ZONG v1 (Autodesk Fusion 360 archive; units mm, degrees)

design "ZONG" references "main 2", "arm cover", "arm main v1", "arm2 v1"
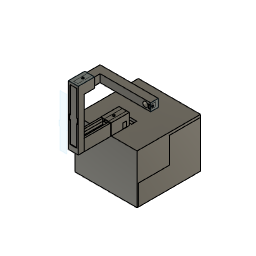
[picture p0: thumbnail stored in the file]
sketch "草图1" plane through (0, 0, 0) normal (0, 0, 1) x axis (1, 0, 0)
  line L1 (60, 60) -> (-60, 60)
  line L2 (60, -60) -> (60, 60)
  line L3 (-60, -60) -> (60, -60)
  line L4 (-60, 60) -> (-60, -60)
  line L5 (60, -60) -> (-60, 60)
  line L6 (-60, -60) -> (60, 60)
  point P6 (0, 0)
  point P1 (0, 0)
  point P4 (60, -60)
  point P5 (-60, -60)
  horizontal L1
  perpendicular L1 L2
  parallel L1 L3
  parallel L2 L4
  coincident L5 P6
  coincident L6 P6
  coincident P1 P6
  dimension "d1" distance P4 P5 = 120
  dimension "d2" distance L1 L3 = 120
sketch "草图2" plane through (0, -60, 0) normal (0, -1, 0) x axis (1, 0, 0)
  line L1 (60, 0) -> (-60, 0)
  line L2 (60, 90) -> (60, 0)
  line L3 (-60, 90) -> (60, 90)
  line L4 (-60, 0) -> (-60, 90)
  line L5 (55, 90) -> (-55, 90)
  line L6 (55, 5) -> (55, 90)
  line L7 (-55, 5) -> (55, 5)
  line L8 (-55, 90) -> (-55, 5)
  point P6 (-55, 90)
  horizontal L5
  vertical L6
  horizontal L7
  vertical L8
  coincident L3 P6
  dimension "d5" distance L4 L8 = 5
  dimension "d19" distance L1 L7 = 5
sketch "草图11" plane through (0, -60, 0) normal (0, -1, 0) x axis (1, 0, 0)
  line L1 (-55, 90) -> (-55, 5)
  line L2 (-60, 90) -> (-55, 90)
  line L3 (-60, 0) -> (-60, 90)
  line L4 (60, 0) -> (-60, 0)
  line L5 (60, 90) -> (60, 0)
  line L6 (55, 90) -> (60, 90)
  line L7 (55, 5) -> (55, 90)
  line L8 (-55, 5) -> (55, 5)
  line L9 (-58, 85) -> (-55, 85)
  line L10 (-58, 75) -> (-58, 85)
  line L11 (-55, 75) -> (-58, 75)
  line L12 (-55, 85) -> (-55, 75)
  point P10 (-55, 85)
  horizontal L9
  vertical L10
  horizontal L11
  vertical L12
  coincident L1 P10
  dimension "d45" distance L10 L12 = 3
  dimension "d46" distance L9 L11 = 10
  dimension "d47" distance L2 L9 = 5
sketch "草图12" plane through (-60, 0, 0) normal (-1, 0, 0) x axis (0, -1, 0)
  line L1 (60, 0) -> (-60, 0)
  line L2 (60, 90) -> (60, 0)
  line L3 (-60, 90) -> (60, 90)
  line L4 (-60, 0) -> (-60, 90)
  line L5 (60, 90) -> (0, 90)
  line L6 (60, 40) -> (60, 90)
  line L7 (0, 40) -> (60, 40)
  line L8 (0, 90) -> (0, 40)
  point P8 (60, 40)
  point P6 (0, 90)
  horizontal L5
  vertical L6
  horizontal L7
  vertical L8
  coincident L2 P8
  midpoint L3 P6
  dimension "d50" distance L5 L7 = 50
sketch "草图13" plane through (0, 0, 0) normal (0, -1, 0) x axis (1, 0, 0)
  line L1 (-55, 90) -> (-55, 40)
  line L2 (-60, 90) -> (-55, 90)
  line L3 (-60, 40) -> (-60, 90)
  line L4 (-55, 40) -> (-60, 40)
  line L5 (-58, 85) -> (-55, 85)
  line L6 (-58, 65) -> (-58, 85)
  line L7 (-55, 65) -> (-58, 65)
  line L8 (-55, 85) -> (-55, 65)
  point P6 (-55, 85)
  horizontal L5
  vertical L6
  horizontal L7
  vertical L8
  coincident L1 P6
  dimension "d53" distance L5 L7 = 20
  dimension "d54" distance L2 L5 = 5
  dimension "d55" distance L6 L8 = 3
mirror "镜像1" mirrorStitchTolerance 0.1
sketch "草图14" plane through (0, -60, 0) normal (0, -1, 0) x axis (1, 0, 0)
  line L1 (-60, 40) -> (-55, 40)
  line L2 (-60, 0) -> (-60, 40)
  line L3 (60, 0) -> (-60, 0)
  line L4 (60, 40) -> (60, 0)
  line L5 (55, 40) -> (60, 40)
  line L6 (55, 5) -> (55, 40)
  line L7 (-55, 5) -> (55, 5)
  line L8 (-55, 40) -> (-55, 5)
  line L9 (-58, 40) -> (-56, 40)
  line L10 (-58, 35) -> (-58, 40)
  line L11 (-56, 35) -> (-58, 35)
  line L12 (-56, 40) -> (-56, 35)
  point P10 (-56, 40)
  horizontal L9
  vertical L10
  horizontal L11
  vertical L12
  coincident L1 P10
  dimension "d60" distance L9 L11 = 5
  dimension "d61" distance L10 L12 = 2
  dimension "d62" distance L2 L10 = 2
mirror "镜像2" mirrorStitchTolerance 0.1
sketch "草图1" plane through (0, -60, 0) normal (0, -1, 0) x axis (1, 0, 0)
  line L1 (58, 35) -> (58, 40)
  line L2 (56, 35) -> (58, 35)
  line L3 (56, 40) -> (56, 35)
  line L4 (55, 40) -> (56, 40)
  line L5 (55, 5) -> (55, 40)
  line L6 (-55, 5) -> (55, 5)
  line L7 (-55, 40) -> (-55, 5)
  line L8 (-56, 40) -> (-55, 40)
  line L9 (-56, 35) -> (-56, 40)
  line L10 (-58, 35) -> (-56, 35)
  line L11 (-58, 40) -> (-58, 35)
  line L12 (-60, 40) -> (-58, 40)
  line L13 (-60, 0) -> (-60, 40)
  line L14 (60, 0) -> (-60, 0)
  line L15 (60, 40) -> (60, 0)
  line L16 (58, 40) -> (60, 40)
  line L17 (-57.9, 35) -> (-56.1, 35)
  line L18 (-57.9, 39.9) -> (-57.9, 35)
  line L19 (-56.1, 39.9) -> (-57.9, 39.9)
  line L20 (-56.1, 35) -> (-56.1, 39.9)
  line L21 (57.9, 40) -> (56.1, 40)
  line L22 (57.9, 35.1) -> (57.9, 40)
  line L23 (56.1, 35.1) -> (57.9, 35.1)
  line L24 (56.1, 40) -> (56.1, 35.1)
  point P18 (-56.1, 35)
  horizontal L17
  vertical L18
  horizontal L19
  vertical L20
  coincident L10 P18
  horizontal L21
  vertical L22
  horizontal L23
  vertical L24
  dimension "d82" distance L17 L19 = 4.9
  dimension "d83" distance L18 L20 = 1.8
  dimension "d84" distance L9 L20 = 0.1
  dimension "d85" distance L22 L24 = 1.8
  dimension "d86" distance L21 L23 = 4.9
  dimension "d87" distance L1 L22 = 0.1
mirror_component "镜像零部件"
derived_instance "DerivedInstance1"
remove_instance "移除实例"
extrude "拉伸6" new body of existing geometry blind 50
sketch "草图2" plane through (0, -60, 0) normal (0, -1, 0) x axis (1, 0, 0)
  line L1 (58, 35) -> (58, 40)
  line L2 (56, 35) -> (58, 35)
  line L3 (56, 40) -> (56, 35)
  line L4 (55, 40) -> (56, 40)
  line L5 (55, 5) -> (55, 40)
  line L6 (-55, 5) -> (55, 5)
  line L7 (-55, 40) -> (-55, 5)
  line L8 (-56, 40) -> (-55, 40)
  line L9 (-56, 35) -> (-56, 40)
  line L10 (-58, 35) -> (-56, 35)
  line L11 (-58, 40) -> (-58, 35)
  line L12 (-60, 40) -> (-58, 40)
  line L13 (-60, 0) -> (-60, 40)
  line L14 (60, 0) -> (-60, 0)
  line L15 (60, 40) -> (60, 0)
  line L16 (58, 40) -> (60, 40)
  line L17 (-60, 95) -> (60, 95)
  line L18 (-60, 0) -> (-60, 95)
  line L19 (60, 0) -> (-60, 0)
  line L20 (60, 95) -> (60, 0)
  point P15 (-60, 0)
  point P20 (-60, 0)
  horizontal L17
  vertical L18
  horizontal L19
  vertical L20
  coincident P15 P20
  dimension "d73" distance L17 L19 = 95
extrude "拉伸2" add sketch "草图2" along normal blind 2.5
sketch "草图3" plane through (0, -60, 0) normal (0, 1, 0) x axis (-1, 0, 0)
  line L1 (-60, 0) -> (-60, 95)
  line L2 (60, 95) -> (60, 0)
  line L3 (-60, 95) -> (60, 95)
  line L4 (60, 95) -> (-60, 95)
  line L5 (60, 90) -> (60, 95)
  line L6 (-60, 90) -> (60, 90)
  line L7 (-60, 95) -> (-60, 90)
  line L8 (60, 0) -> (-60, 0)
  line L9 (-56, 40) -> (-58, 40)
  line L10 (-56, 35) -> (-56, 40)
  line L11 (-58, 35) -> (-56, 35)
  line L12 (-58, 40) -> (-58, 35)
  point P8 (60, 90)
  point P2 (-60, 95)
  point P6 (-60, 95)
  horizontal L4
  vertical L5
  horizontal L6
  vertical L7
  coincident L2 P8
  coincident P2 P6
extrude "拉伸3" add sketch "草图3" profile of L1 L2 L3 L4 L5 L6 L7 along normal blind 120
sketch "草图4" plane through (60, 0, 0) normal (1, 0, 0) x axis (0, 1, 0)
  line L1 (-60, 90) -> (-60, 0)
  line L2 (60, 90) -> (-60, 90)
  line L3 (60, 95) -> (60, 90)
  line L4 (-62.5, 95) -> (60, 95)
  line L5 (-62.5, 0) -> (-62.5, 95)
  line L6 (-60, 0) -> (-62.5, 0)
  line L7 (-60, 90) -> (0, 90)
  line L8 (-60, 40) -> (-60, 90)
  line L9 (0, 40) -> (-60, 40)
  line L10 (0, 90) -> (0, 40)
  point P10 (-60, 40)
  point P8 (0, 90)
  horizontal L7
  vertical L8
  horizontal L9
  vertical L10
  coincident L1 P10
  midpoint L2 P8
extrude "拉伸4" add sketch "草图4" profile of L1 L2 L7 L8 L9 L10 against normal blind 5
sketch "草图5" plane through (0, 0, 0) normal (0, 1, 0) x axis (-1, 0, 0)
  line L1 (-60, 40) -> (-60, 90)
  line L2 (-55, 40) -> (-60, 40)
  line L3 (-55, 90) -> (-55, 40)
  line L4 (-60, 90) -> (-55, 90)
  line L5 (-55, 65.1) -> (-58, 65.1)
  line L6 (-55, 84.9) -> (-55, 65.1)
  line L7 (-58, 84.9) -> (-55, 84.9)
  line L8 (-58, 65.1) -> (-58, 84.9)
  point P8 (-55, 84.9)
  horizontal L5
  vertical L6
  horizontal L7
  vertical L8
  coincident L3 P8
  dimension "d80" distance L4 L7 = 5.1
  dimension "d81" distance L5 L7 = 19.8
extrude "拉伸5" add sketch "草图5" profile of L3 L5 L6 L7 L8 along normal blind 9.8
mirror "镜像2" mirrorStitchTolerance 0.1
mirror "镜像3" mirrorStitchTolerance 0.1
mirror "镜像4" mirrorStitchTolerance 0.1
sketch "草图2" plane through (0, 0, 95) normal (0, 0, 1) x axis (-1, 0, 0)
  line L1 (60, 62.5) -> (60, -60)
  line L2 (-60, 62.5) -> (60, 62.5)
  line L3 (-60, -60) -> (-60, 62.5)
  line L4 (60, -60) -> (-60, -60)
  line L5 (-10, 50) -> (10, 50)
  line L6 (-10, 15) -> (-10, 50)
  line L7 (10, 15) -> (-10, 15)
  line L8 (10, 50) -> (10, 15)
  horizontal L5
  vertical L6
  horizontal L7
  vertical L8
  dimension "d96" distance L6 L8 = 20
  dimension "d97" distance L5 L7 = 35
extrude "拉伸1" new body sketch "草图2" profile of L5 L6 L7 L8 along normal blind 20
sketch "草图3" plane through (0, -15, 0) normal (0, 1, 0) x axis (-1, 0, 0)
  line L1 (10, 95) -> (-10, 95)
  line L2 (10, 115) -> (10, 95)
  line L3 (-10, 115) -> (10, 115)
  line L4 (-10, 95) -> (-10, 115)
  line L5 (-6.2, 111.8736) -> (-6.2, 112)
  line L6 (-6, 101.3) -> (-6.2, 101.3)
  line L7 (6.5, 101.3) -> (6.35, 101.3)
  line L8 (6.35, 112) -> (-6.35, 112)
  line L9 (6.35, 101.3) -> (6.35, 112)
  line L10 (-6.35, 112) -> (-6.35, 101.3)
  line L11 (5.4209, 102.0827) -> (-6.35, 112)
  line L12 (-6.35, 101.3) -> (6.35, 112)
  line L13 (3.9991, 99.3) -> (3.9991, 101.3)
  line L14 (-4.0009, 99.3) -> (3.9991, 99.3)
  line L15 (-4.0009, 101.3) -> (-4.0009, 99.3)
  line L16 (3.9991, 99.3) -> (-4.0009, 101.3)
  line L17 (-4.0009, 99.3) -> (3.9991, 101.3)
  line L18 (3.9991, 101.3) -> (6.35, 101.3)
  line L19 (-6.35, 101.3) -> (-4.0009, 101.3)
  line L20 (3.9991, 99.3) -> (3.9991, 101.3)
  line L21 (-4.0009, 101.3) -> (-4.0009, 99.3)
  line L22 (3.9991, 99.3) -> (3.9991, 101.3)
  point P13 (0, 106.65)
  point P14 (-6.2, 112)
  point P15 (-6.2, 111.8736)
  point P17 (6.35, 101.3)
  point P22 (-0.0009, 100.3)
  point P18 (-4.0009, 101.3)
  point P21 (-4.0009, 99.3)
  vertical L5
  horizontal L6
  collinear L6 L7
  horizontal L8
  perpendicular L8 L9
  parallel L8 L18
  parallel L9 L10
  coincident L11 P13
  coincident L12 P13
  coincident L8 P14
  coincident L11 P15
  coincident L9 P17
  parallel L13 L15
  coincident L16 P22
  coincident L17 P22
  coincident P18 L18
  collinear L18 L19
  perpendicular L14 L20
  perpendicular L19 L21
  dimension "d176" distance L8 L18 = 10.7
  dimension "d177" distance L9 L10 = 12.7
  dimension "d178" distance L3 L8 = 3
  dimension "d179" distance L2 L9 = 3.65
  dimension "d180" distance P18 P21 = 2
  dimension "d181" distance L13 L15 = 8
sketch "草图4" plane through (0, 0, 95) normal (0, 0, -1) x axis (1, 0, 0)
  line L1 (-10, 15) -> (-10, 50)
  line L2 (10, 15) -> (-10, 15)
  line L3 (10, 50) -> (10, 15)
  line L4 (-10, 50) -> (10, 50)
  line L5 (-7.391, 41) -> (7.609, 41)
  line L6 (-7.391, 36) -> (-7.391, 41)
  line L7 (7.609, 36) -> (-7.391, 36)
  line L8 (7.609, 41) -> (7.609, 36)
  horizontal L5
  vertical L6
  horizontal L7
  vertical L8
  dimension "d107" distance L5 L7 = 5
  dimension "d108" distance L6 L8 = 15
sketch "草图5" plane through (0, 0, 0) normal (0, 0, -1) x axis (1, 0, 0)
  line L1 (-60, 60) -> (60, 60)
  line L2 (-60, -60) -> (-60, 60)
  line L3 (60, -60) -> (-60, -60)
  line L4 (60, 60) -> (60, -60)
  line L5 (-32, -40) -> (-45, -40)
  line L6 (-32, -52) -> (-32, -40)
  line L7 (-45, -52) -> (-32, -52)
  line L8 (-45, -40) -> (-45, -52)
  horizontal L5
  vertical L6
  horizontal L7
  vertical L8
  dimension "d113" distance L5 L7 = 12
  dimension "d114" distance L6 L8 = 13
  dimension "d115" distance L2 L8 = 15
sketch "草图6" plane through (0, 0, 90) normal (0, 0, -1) x axis (1, 0, 0)
  line L1 (-60, 0) -> (-55, 0)
  line L2 (-60, -60) -> (-60, 0)
  line L3 (60, -60) -> (-60, -60)
  line L4 (60, 0) -> (60, -60)
  line L5 (55, 0) -> (60, 0)
  line L6 (55, 60) -> (55, 0)
  line L7 (-55, 60) -> (55, 60)
  line L8 (-55, 0) -> (-55, 60)
  line L9 (-7.4, 36) -> (7.6, 36)
  line L10 (-7.4, 46) -> (-7.4, 36)
  line L11 (7.6, 46) -> (-7.4, 46)
  line L12 (7.6, 36) -> (7.6, 46)
  horizontal L9
  vertical L10
  horizontal L11
  vertical L12
  dimension "d161" distance L9 L11 = 10
position "位置"
extrude "拉伸9" cut of existing geometry blind -1
extrude "拉伸10" cut of existing geometry blind -1
extrude "拉伸11" cut of existing geometry blind -1
extrude "拉伸12" cut of existing geometry blind -1
extrude "拉伸13" cut of existing geometry blind -1
extrude "拉伸14" cut of existing geometry blind -1
extrude "拉伸15" cut of existing geometry blind -0.5
extrude "拉伸16" cut of existing geometry blind -0.5
extrude "拉伸17" cut of existing geometry blind -0.5
extrude "拉伸18" cut of existing geometry blind -0.5
extrude "拉伸15" add of existing geometry blind 2
sketch "草图15" plane through (0, -62.5, 0) normal (0, -1, 0) x axis (1, 0, 0)
  line L1 (10, 95) -> (-10, 95)
  line L2 (10, 117) -> (10, 95)
  line L3 (-10, 117) -> (10, 117)
  line L4 (-10, 95) -> (-10, 117)
  line L5 (-4, 113) -> (4, 113)
  line L6 (-4, 116) -> (-4, 113)
  line L7 (4, 116) -> (-4, 116)
  line L8 (4, 113) -> (4, 116)
  line L9 (-4, 116) -> (4, 113)
  line L10 (4, 116) -> (-4, 113)
  point P10 (0, 114.5)
  point P8 (-4, 116)
  point P9 (4, 116)
  horizontal L5
  perpendicular L5 L6
  parallel L5 L7
  parallel L6 L8
  coincident L9 P10
  coincident L10 P10
  dimension "d151" distance P8 P9 = 8
  dimension "d152" distance L5 L7 = 3
extrude "拉伸7" cut sketch "草图15" profile of L5 L6 L7 L8 against normal blind 50
sketch "草图16" plane through (0, 0, 117) normal (0, 0, 1) x axis (-1, 0, 0)
  line L1 (10, 62.5) -> (10, 27.5)
  line L2 (-10, 62.5) -> (10, 62.5)
  line L3 (-10, 27.5) -> (-10, 62.5)
  line L4 (10, 27.5) -> (-10, 27.5)
  circle C1 centre (0, 47.5) radius 2
  point P6 (0, 47.5)
  dimension "d155" diameter C1 = 4
  dimension "d156" distance L2 P6 = 15
extrude "拉伸8" cut sketch "草图16" profile of C1 against normal blind 7
extrude "拉伸9" add of existing geometry blind 1
extrude "拉伸10" add of existing geometry blind 1
sketch "草图18" plane through (0, 0, 90) normal (0, 0, -1) x axis (1, 0, 0)
  line L1 (-60, 0) -> (-55, 0)
  line L2 (-60, -60) -> (-60, 0)
  line L3 (60, -60) -> (-60, -60)
  line L4 (60, 0) -> (60, -60)
  line L5 (55, 0) -> (60, 0)
  line L6 (55, 60) -> (55, 0)
  line L7 (-55, 60) -> (55, 60)
  line L8 (-55, 0) -> (-55, 60)
  line L9 (7.6149, 46) -> (-7.4, 46)
  line L10 (7.6149, 39) -> (7.6149, 46)
  line L11 (-7.4, 39) -> (7.6149, 39)
  line L12 (-7.4, 46) -> (-7.4, 39)
  horizontal L9
  vertical L10
  horizontal L11
  vertical L12
  dimension "d184" distance L9 L11 = 7
sketch "草图19" plane through (0, 0, 95) normal (0, 0, 1) x axis (-1, 0, 0)
  line L1 (60, 62.5) -> (60, -60)
  line L2 (-60, 62.5) -> (60, 62.5)
  line L3 (-60, -60) -> (-60, 62.5)
  line L4 (60, -60) -> (-60, -60)
  line L5 (-10, 13) -> (10, 13)
  line L6 (-10, 23) -> (-10, 13)
  line L7 (10, 23) -> (-10, 23)
  line L8 (10, 13) -> (10, 23)
  line L9 (-10, 23) -> (10, 13)
  line L10 (10, 23) -> (-10, 13)
  point P10 (0, 18)
  horizontal L5
  perpendicular L5 L6
  parallel L5 L7
  parallel L6 L8
  coincident L9 P10
  coincident L10 P10
extrude "拉伸21" cut sketch "草图19" profile of L5 L6 L7 L8 against normal blind 30
extrude "拉伸12" cut sketch "草图3" profile of L7 L8 L9 L19 L10 L13 L14 L15 L20 L21 L22 against normal blind 55
sketch "草图20" plane through (0, 0, 90) normal (0, 0, -1) x axis (1, 0, 0)
  line L1 (10, 13) -> (10, 23)
  line L2 (-10, 13) -> (10, 13)
  line L3 (-10, 23) -> (-10, 13)
  line L4 (10, 23) -> (-10, 23)
  line L5 (-60, 0) -> (-55, 0)
  line L6 (-60, -60) -> (-60, 0)
  line L7 (60, -60) -> (-60, -60)
  line L8 (60, 0) -> (60, -60)
  line L9 (55, 0) -> (60, 0)
  line L10 (55, 60) -> (55, 0)
  line L11 (-55, 60) -> (55, 60)
  line L12 (-55, 0) -> (-55, 60)
  line L13 (9.625, 39.5) -> (-9.625, 39.5)
  line L14 (9.625, 32.5) -> (9.625, 39.5)
  line L15 (-9.625, 32.5) -> (9.625, 32.5)
  line L16 (-9.625, 39.5) -> (-9.625, 32.5)
  line L17 (9.625, 32.5) -> (-9.625, 39.5)
  line L18 (-9.625, 32.5) -> (9.625, 39.5)
  line L19 (60, 62.5) -> (-60, 62.5)
  point P18 (0, 36)
  horizontal L13
  perpendicular L13 L14
  parallel L13 L15
  parallel L14 L16
  coincident L17 P18
  coincident L18 P18
  dimension "d185" distance L13 L15 = 7
  dimension "d186" distance L13 L19 = 23
extrude "拉伸22" cut sketch "草图20" profile of L13 L14 L15 L16 against normal blind 15
component_insert "插入零部件1"
component_insert "插入零部件2"
component_insert "插入零部件3"
component_insert "插入零部件6"
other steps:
extrude "拉伸5" add of existing geometry blind 2
extrude "拉伸13" cut sketch "草图20" profile of L13 L14 L15 L16 against normal blind 15
derived_base_feature "Derived Base Feature"
create_component "创建零部件1"
create_component "创建零部件2"
create_component "创建零部件3"

design "arm main v1"
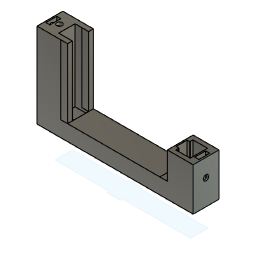
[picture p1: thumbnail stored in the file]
sketch "草图1" plane through (0, 0, 0) normal (0, 0, 1) x axis (1, 0, 0)
  line L1 (57.5, 9.5) -> (-57.5, 9.5)
  line L2 (57.5, -9.5) -> (57.5, 9.5)
  line L3 (-57.5, -9.5) -> (57.5, -9.5)
  line L4 (-57.5, 9.5) -> (-57.5, -9.5)
  line L5 (57.5, -9.5) -> (-57.5, 9.5)
  line L6 (-57.5, -9.5) -> (57.5, 9.5)
  point P6 (0, 0)
  point P1 (0, 0)
  point P4 (57.5, -9.5)
  point P5 (-57.5, -9.5)
  horizontal L1
  perpendicular L1 L2
  parallel L1 L3
  parallel L2 L4
  coincident L5 P6
  coincident L6 P6
  coincident P1 P6
  dimension "d1" distance P4 P5 = 115
  dimension "d2" distance L1 L3 = 19
extrude "拉伸1" new body sketch "草图1" profile of L1 L2 L3 L4 along normal blind 10
sketch "草图2" plane through (0, 0, 10) normal (0, 0, 1) x axis (-1, 0, 0)
  line L1 (-57.5, 9.5) -> (57.5, 9.5)
  line L2 (-57.5, -9.5) -> (-57.5, 9.5)
  line L3 (57.5, -9.5) -> (-57.5, -9.5)
  line L4 (57.5, 9.5) -> (57.5, -9.5)
  line L5 (-38.5, 9.5) -> (-57.5, 9.5)
  line L6 (-38.5, -9.5) -> (-38.5, 9.5)
  line L7 (-57.5, -9.5) -> (-38.5, -9.5)
  line L8 (-57.5, 9.5) -> (-57.5, -9.5)
  point P3 (-57.5, 9.5)
  point P6 (-57.5, 9.5)
  point P7 (-38.5, 9.5)
  horizontal L5
  vertical L6
  horizontal L7
  vertical L8
  coincident P3 P6
  dimension "d5" distance P6 P7 = 19
extrude "拉伸2" add sketch "草图2" profile of L1 L2 L3 L5 L6 L7 L8 along normal blind 20
sketch "草图3" plane through (0, 0, 30) normal (0, 0, 1) x axis (-1, 0, 0)
  line L1 (-38.5, -9.5) -> (-57.5, -9.5)
  line L2 (-38.5, 9.5) -> (-38.5, -9.5)
  line L3 (-57.5, 9.5) -> (-38.5, 9.5)
  line L4 (-57.5, -9.5) -> (-57.5, 9.5)
  line L5 (-41.5, 6.353) -> (-52.2, 6.353)
  line L6 (-52.2, -6.347) -> (-41.5, -6.347)
  line L7 (-41.5, -6.347) -> (-52.2, 6.353)
  line L8 (-52.2, -6.347) -> (-41.5, 6.353)
  line L9 (-52.2, -5.5) -> (-52.2, -6.347)
  line L10 (-52.2, 6.353) -> (-52.2, 5.5)
  line L11 (-52.2, -5.5) -> (-52.2, 5.5)
  line L12 (-41.5, 4.5005) -> (-41.5, 6.353)
  line L13 (-41.5, -6.347) -> (-41.5, -4.4995)
  line L14 (-39.5, 3.9901) -> (-41.5, 3.9901)
  line L15 (-39.5, -4.0099) -> (-39.5, 3.9901)
  line L16 (-41.5, -4.0099) -> (-39.5, -4.0099)
  line L17 (-39.5, -4.0099) -> (-41.5, 3.9901)
  line L18 (-41.5, -4.0099) -> (-39.5, 3.9901)
  line L19 (-56.2, 4) -> (-53.2, 4)
  line L20 (-56.2, -4) -> (-56.2, 4)
  line L21 (-53.2, -4) -> (-56.2, -4)
  line L22 (-53.2, 4) -> (-53.2, -4)
  line L23 (-56.2, -4) -> (-53.2, 4)
  line L24 (-53.2, -4) -> (-56.2, 4)
  line L25 (-41.5, 3.9901) -> (-41.5, 4.5005)
  line L26 (-41.5, -4.4995) -> (-41.5, -4.0099)
  point P10 (-46.85, 0.003)
  point P11 (-52.2, 5.5)
  point P20 (-40.5, -0.0099)
  point P15 (-40.5, -0.0099)
  point P25 (-54.7, 0)
  point P26 (-41.5, 3.9901)
  point P18 (-39.5, -4.0099)
  point P19 (-41.5, -4.0099)
  horizontal L5
  perpendicular L5 L12
  parallel L5 L6
  parallel L9 L12
  coincident L7 P10
  coincident L8 P10
  coincident P11 L9
  collinear L9 L10
  collinear L12 L13
  parallel L13 L25
  horizontal L14
  perpendicular L14 L15
  parallel L14 L16
  coincident L17 P20
  coincident L18 P20
  coincident P15 P20
  horizontal L19
  perpendicular L19 L20
  parallel L19 L21
  parallel L20 L22
  coincident L23 P25
  coincident L24 P25
  collinear L25 L26
  coincident L17 P26
  dimension "d24" distance L9 L12 = 10.7
  dimension "d25" distance L5 L6 = 12.7
  dimension "d26" distance L2 L12 = 3
  dimension "d32" distance P18 P19 = 2
  dimension "d33" distance L14 L16 = 8
  dimension "d34" distance P15 L25 = 1
  dimension "d35" distance L19 L21 = 8
  dimension "d36" distance L20 L22 = 3
  dimension "d37" distance L11 L22 = 1
sketch "草图4" plane through (38.5, 0, 0) normal (-1, 0, 0) x axis (0, -1, 0)
  line L1 (9.5, 10) -> (-9.5, 10)
  line L2 (9.5, 30) -> (9.5, 10)
  line L3 (-9.5, 30) -> (9.5, 30)
  line L4 (-9.5, 10) -> (-9.5, 30)
  circle C1 centre (0, 17) radius 2
  point P6 (0, 17)
  dimension "d20" diameter C1 = 4
  dimension "d21" distance L3 P6 = 13
extrude "拉伸6" cut sketch "草图3" profile of L5 L13 L6 L10 L11 L26 L14 L15 L16 against normal blind 47
extrude "拉伸7" cut sketch "草图3" profile of L19 L20 L21 L22 against normal blind 17
sketch "草图5" plane through (57.5, 0, 0) normal (1, 0, 0) x axis (0, 1, 0)
  line L1 (9.5, 0) -> (-9.5, 0)
  line L2 (9.5, 30) -> (9.5, 0)
  line L3 (-9.5, 30) -> (9.5, 30)
  line L4 (-9.5, 0) -> (-9.5, 30)
  circle C1 centre (0, 22) radius 2
  point P6 (0, 22)
  dimension "d42" diameter C1 = 4
  dimension "d43" distance L3 P6 = 8
extrude "拉伸8" cut sketch "草图5" profile of C1 against normal blind 13
sketch "草图6" plane through (0, 0, 10) normal (0, 0, 1) x axis (-1, 0, 0)
  line L1 (-38.5, -9.5) -> (-38.5, 9.5)
  line L2 (57.5, -9.5) -> (-38.5, -9.5)
  line L3 (57.5, 9.5) -> (57.5, -9.5)
  line L4 (-38.5, 9.5) -> (57.5, 9.5)
  line L5 (56.5, -4) -> (53.5, -4)
  line L6 (56.5, 4) -> (56.5, -4)
  line L7 (53.5, 4) -> (56.5, 4)
  line L8 (53.5, -4) -> (53.5, 4)
  line L9 (56.5, 4) -> (53.5, -4)
  line L10 (53.5, 4) -> (56.5, -4)
  circle C1 centre (50.5, 0) radius 2
  point P10 (55, 0)
  point P8 (56.5, 4)
  point P9 (53.5, 4)
  point P11 (50.5, 0)
  horizontal L5
  perpendicular L5 L6
  parallel L5 L7
  parallel L6 L8
  coincident L9 P10
  coincident L10 P10
  dimension "d48" distance P8 P9 = 3
  dimension "d49" distance L5 L7 = 8
  dimension "d131" diameter C1 = 4
  dimension "d132" distance L8 P11 = 3
extrude "拉伸10" cut sketch "草图6" profile of L5 L6 L7 L8 against normal blind 8
sketch "草图7" plane through (-57.5, 0, 0) normal (-1, 0, 0) x axis (0, -1, 0)
  line L1 (9.5, 0) -> (-9.5, 0)
  line L2 (9.5, 10) -> (9.5, 0)
  line L3 (-9.5, 10) -> (9.5, 10)
  line L4 (-9.5, 0) -> (-9.5, 10)
  circle C1 centre (0, 6) radius 2
  point P6 (0, 6)
  dimension "d56" diameter C1 = 4
  dimension "d57" distance L3 P6 = 4
sketch "草图9" plane through (0, 0, 0) normal (0, 0, -1) x axis (1, 0, 0)
  line L1 (-57.5, 9.5) -> (57.5, 9.5)
  line L2 (-57.5, -9.5) -> (-57.5, 9.5)
  line L3 (57.5, -9.5) -> (-57.5, -9.5)
  line L4 (57.5, 9.5) -> (57.5, -9.5)
  line L5 (-47.5, 6.3532) -> (52.5, 6.3532)
  line L6 (-47.5, -6.6468) -> (-47.5, 6.3532)
  line L7 (52.5, -6.6468) -> (-47.5, -6.6468)
  line L8 (52.5, 6.3532) -> (52.5, -6.6468)
  line L9 (41.5, -6.347) -> (52.2, -6.347)
  line L10 (41.5, -4.4995) -> (41.5, -6.347)
  line L11 (41.5, -4.0099) -> (41.5, -4.4995)
  line L12 (39.5, -4.0099) -> (41.5, -4.0099)
  line L13 (39.5, 3.9901) -> (39.5, -4.0099)
  line L14 (41.5, 3.9901) -> (39.5, 3.9901)
  line L15 (41.5, 4.5005) -> (41.5, 3.9901)
  line L16 (41.5, 6.353) -> (41.5, 4.5005)
  line L17 (52.2, 6.353) -> (41.5, 6.353)
  line L18 (52.2, -6.347) -> (52.2, 6.353)
  horizontal L5
  vertical L6
  horizontal L7
  vertical L8
  dimension "d70" distance L6 L8 = 100
  dimension "d71" distance L5 L7 = 13
extrude "拉伸12" cut sketch "草图9" profile of L5 L6 L7 against normal blind 3
sketch "草图10" plane through (0, 0, 3) normal (0, 0, -1) x axis (1, 0, 0)
  line L1 (41.5, -6.347) -> (52.2, -6.347)
  line L2 (52.2, 6.353) -> (41.5, 6.353)
  line L3 (-47.5, -6.6468) -> (-47.5, 6.3532)
  line L4 (56.2, -6.347) -> (52.2, -6.347)
  line L5 (56.2, 6.353) -> (56.2, -6.347)
  line L6 (52.2, 6.353) -> (56.2, 6.353)
  line L7 (52.2, -6.347) -> (52.2, 6.353)
  line L8 (52.5, 6.3532) -> (52.5, -6.6468)
  line L9 (41.5, 3.9901) -> (39.5, 3.9901)
  line L10 (41.5, 4.5005) -> (41.5, 3.9901)
  line L11 (41.5, 6.353) -> (41.5, 4.5005)
  line L12 (52.2, -6.347) -> (52.2, 6.353)
  line L13 (41.5, -4.4995) -> (41.5, -6.347)
  line L14 (41.5, -4.0099) -> (41.5, -4.4995)
  line L15 (39.5, -4.0099) -> (41.5, -4.0099)
  line L16 (39.5, 3.9901) -> (39.5, -4.0099)
  line L17 (-47.5, 6.3532) -> (52.5, 6.3532)
  line L18 (52.5, -6.6468) -> (-47.5, -6.6468)
  point P8 (56.2, 6.353)
  point P2 (52.2, -6.347)
  point P6 (52.2, -6.347)
  horizontal L4
  vertical L5
  horizontal L6
  vertical L7
  coincident L2 P8
  coincident P2 P6
  dimension "d65" distance L5 L7 = 4
extrude "拉伸14" cut sketch "草图10" profile of L1 L2 L3 L4 L5 L6 L7 against normal blind 19
sketch "草图12" plane through (0, 0, 0) normal (0, 0, -1) x axis (1, 0, 0)
  line L1 (-57.5, 9.5) -> (57.5, 9.5)
  line L2 (-57.5, -9.5) -> (-57.5, 9.5)
  line L3 (57.5, -9.5) -> (-57.5, -9.5)
  line L4 (57.5, 9.5) -> (57.5, -9.5)
  line L5 (-47.5, -6.6468) -> (52.5, -6.6468)
  line L6 (-47.5, 6.3532) -> (-47.5, -6.6468)
  line L7 (52.5, 6.3532) -> (-47.5, 6.3532)
  line L8 (2.5, -8) -> (-7.5, -8)
  line L9 (2.5, 8) -> (2.5, -8)
  line L10 (-7.5, 8) -> (2.5, 8)
  line L11 (-7.5, -8) -> (-7.5, 8)
  line L12 (52.5, -6.6468) -> (52.5, 6.3532)
  horizontal L8
  vertical L9
  horizontal L10
  vertical L11
  dimension "d68" distance L9 L11 = 10
  dimension "d69" distance L8 L10 = 16
  dimension "d72" distance L6 L11 = 40
extrude "拉伸17" add of existing geometry blind 1.5
sketch "草图14" plane through (0, 0, -1.5) normal (0, 0, -1) x axis (1, 0, 0)
  line L1 (-57.5, 9.5) -> (57.5, 9.5)
  line L2 (-57.5, -9.5) -> (-57.5, 9.5)
  line L3 (57.5, -9.5) -> (-57.5, -9.5)
  line L4 (57.5, 9.5) -> (57.5, -9.5)
  line L5 (-47.5, -6.6468) -> (52.5, -6.6468)
  line L6 (-47.5, 6.3532) -> (-47.5, -6.6468)
  line L7 (52.5, 6.3532) -> (-47.5, 6.3532)
  line L8 (52.5, -6.6468) -> (52.5, 6.3532)
  circle C1 centre (-51.5, 0) radius 1.5
extrude "拉伸18" add sketch "草图14" profile of C1 against normal blind 1
sketch "草图15" plane through (0, 0, -1.5) normal (0, 0, -1) x axis (1, 0, 0)
  line L1 (-57.5, 9.5) -> (57.5, 9.5)
  line L2 (-57.5, -9.5) -> (-57.5, 9.5)
  line L3 (57.5, -9.5) -> (-57.5, -9.5)
  line L4 (57.5, 9.5) -> (57.5, -9.5)
  line L5 (-47.5, -6.6468) -> (52.5, -6.6468)
  line L6 (-47.5, 6.3532) -> (-47.5, -6.6468)
  line L7 (52.5, 6.3532) -> (-47.5, 6.3532)
  line L8 (2.5, -8) -> (-7.5, -8)
  line L9 (2.5, -6.6468) -> (2.5, -8)
  line L10 (-7.5, -6.6468) -> (2.5, -6.6468)
  line L11 (-7.5, -8) -> (-7.5, -6.6468)
  line L12 (-7.5, 6.3532) -> (2.5, 6.3532)
  line L13 (-7.5, 8) -> (-7.5, 6.3532)
  line L14 (2.5, 8) -> (-7.5, 8)
  line L15 (2.5, 6.3532) -> (2.5, 8)
  line L16 (52.5, -6.6468) -> (52.5, 6.3532)
  point P12 (2.5, -6.6468)
  point P14 (2.5, 6.3532)
  horizontal L8
  vertical L9
  horizontal L10
  vertical L11
  midpoint L5 P12
  horizontal L12
  vertical L13
  horizontal L14
  vertical L15
  midpoint L7 P14
extrude "拉伸19" cut sketch "草图15" profile of L5 L7 L8 L9 L10 L11 L12 L13 L14 L15 against normal blind 1
sketch "草图16" plane through (0, 0, -21) normal (0, 0, -1) x axis (1, 0, 0)
  line L1 (-7.5, 8) -> (2.5, 8)
  line L2 (-7.5, 6.3532) -> (-7.5, 8)
  line L3 (-47.5, 6.3532) -> (-7.5, 6.3532)
  line L4 (-47.5, -6.6468) -> (-47.5, 6.3532)
  line L5 (-7.5, -6.6468) -> (-47.5, -6.6468)
  line L6 (-7.5, -8) -> (-7.5, -6.6468)
  line L7 (2.5, -8) -> (-7.5, -8)
  line L8 (2.5, -6.6468) -> (2.5, -8)
  line L9 (52.5, -6.6468) -> (2.5, -6.6468)
  line L10 (52.5, 6.3532) -> (52.5, -6.6468)
  line L11 (2.5, 6.3532) -> (52.5, 6.3532)
  line L12 (2.5, 8) -> (2.5, 6.3532)
sketch "草图17" plane through (0, 0, 10) normal (0, 0, 1) x axis (-1, 0, 0)
  line L1 (53.5, -4) -> (56.5, -4)
  line L2 (53.5, 4) -> (53.5, -4)
  line L3 (56.5, 4) -> (53.5, 4)
  line L4 (56.5, -4) -> (56.5, 4)
  line L5 (-38.5, -9.5) -> (-38.5, 9.5)
  line L6 (57.5, -9.5) -> (-38.5, -9.5)
  line L7 (57.5, 9.5) -> (57.5, -9.5)
  line L8 (-38.5, 9.5) -> (57.5, 9.5)
extrude "拉伸20" add sketch "草图17" along normal blind 11
sketch "草图19" plane through (0, 9.5, 0) normal (0, 1, 0) x axis (-1, 0, 0)
  line L1 (57.5, 10) -> (-38.5, 10)
  line L2 (57.5, 21) -> (57.5, 10)
  line L3 (-38.5, 21) -> (57.5, 21)
  line L4 (-33, 21) -> (40, 21)
  line L5 (40, 10) -> (-33, 10)
  line L6 (40, 21) -> (40, 10)
  line L7 (-33, 21) -> (-33, 10)
  line L8 (-38.5, 10) -> (-38.5, 21)
  point P6 (40, 21)
  horizontal L4
  horizontal L5
  vertical L6
  coincident L3 P6
extrude "拉伸22" cut sketch "草图19" profile of L1 L3 L4 L5 L6 L7 against normal blind 30
extrude "拉伸25" cut sketch "草图6" profile of C1 along normal blind 16
sketch "草图22" plane through (0, -9.5, 0) normal (0, -1, 0) x axis (1, 0, 0)
  line L1 (33, 10) -> (33, 21)
  line L2 (-40, 10) -> (33, 10)
  line L3 (-40, 21) -> (-40, 10)
  line L4 (-57.5, 21) -> (-40, 21)
  line L5 (-57.5, -1.5) -> (-57.5, 21)
  line L6 (57.5, -1.5) -> (-57.5, -1.5)
  line L7 (57.5, 30) -> (57.5, -1.5)
  line L8 (38.5, 30) -> (57.5, 30)
  line L9 (38.5, 21) -> (38.5, 30)
  line L10 (33, 21) -> (38.5, 21)
  line L11 (38.5, 10) -> (33, 10)
  line L12 (38.5, 21) -> (38.5, 10)
  line L13 (33, 21) -> (38.5, 21)
  line L14 (33, 10) -> (33, 21)
  point P11 (38.5, 21)
  point P14 (38.5, 21)
  point P3 (33, 10)
  point P12 (33, 10)
  horizontal L11
  vertical L12
  horizontal L13
  vertical L14
  coincident P11 P14
  coincident P3 P12
extrude "拉伸26" cut sketch "草图22" profile of L1 L10 L11 L12 L13 L14 against normal blind 70
sketch "草图23" plane through (0, 0, 30) normal (0, 0, 1) x axis (-1, 0, 0)
  line L1 (-53.2, 4) -> (-56.2, 4)
  line L2 (-53.2, -4) -> (-53.2, 4)
  line L3 (-56.2, -4) -> (-53.2, -4)
  line L4 (-56.2, 4) -> (-56.2, -4)
  line L5 (-52.2, -6.347) -> (-41.5, -6.347)
  line L6 (-52.2, 6.353) -> (-52.2, -6.347)
  line L7 (-41.5, 6.353) -> (-52.2, 6.353)
  line L8 (-41.5, 4.5005) -> (-41.5, 6.353)
  line L9 (-41.5, 3.9901) -> (-41.5, 4.5005)
  line L10 (-39.5, 3.9901) -> (-41.5, 3.9901)
  line L11 (-39.5, -4.0099) -> (-39.5, 3.9901)
  line L12 (-41.5, -4.0099) -> (-39.5, -4.0099)
  line L13 (-41.5, -4.4995) -> (-41.5, -4.0099)
  line L14 (-41.5, -6.347) -> (-41.5, -4.4995)
  line L15 (-38.5, -9.5) -> (-57.5, -9.5)
  line L16 (-38.5, 9.5) -> (-38.5, -9.5)
  line L17 (-57.5, 9.5) -> (-38.5, 9.5)
  line L18 (-57.5, -9.5) -> (-57.5, 9.5)
extrude "拉伸27" add sketch "草图23" against normal blind 27
sketch "草图24" plane through (57.5, 0, 0) normal (1, 0, 0) x axis (0, 1, 0)
  line L1 (-9.5, -1.5) -> (-9.5, 30)
  line L2 (9.5, -1.5) -> (-9.5, -1.5)
  line L3 (9.5, 30) -> (9.5, -1.5)
  line L4 (-9.5, 30) -> (9.5, 30)
sketch "草图25" plane through (57.5, 0, 0) normal (1, 0, 0) x axis (0, 1, 0)
  line L1 (-9.5, 30) -> (9.5, 30)
  circle C1 centre (0, 17) radius 2
  point P2 (0, 17)
  dimension "d139" diameter C1 = 4
  dimension "d140" distance P2 L1 = 13
extrude "拉伸28" cut sketch "草图25" profile of C1 against normal blind 11
extrude "拉伸29" cut of existing geometry blind -5
sketch "草图26" plane through (0, 0, 10) normal (0, 0, 1) x axis (-1, 0, 0)
  line L1 (-33, 9.5) -> (40, 9.5)
  line L2 (-33, -9.5) -> (-33, 9.5)
  line L3 (40, -9.5) -> (-33, -9.5)
  line L4 (40, 9.5) -> (40, -9.5)
  line L5 (45, -6) -> (35, -6)
  line L6 (45, 6) -> (45, -6)
  line L7 (35, 6) -> (45, 6)
  line L8 (35, -6) -> (35, 6)
  line L9 (45, 6) -> (35, -6)
  line L10 (35, 6) -> (45, -6)
  point P10 (40, 0)
  horizontal L5
  perpendicular L5 L6
  parallel L5 L7
  parallel L6 L8
  coincident L9 P10
  coincident L10 P10
  midpoint L4 P10
extrude "拉伸30" cut sketch "草图26" profile of L4 L5 L7 L8 against normal blind 27
sketch "草图27" plane through (0, 0, 8) normal (0, 0, -1) x axis (1, 0, 0)
  line L1 (-40, -6) -> (-35, -6)
  line L2 (-40, 6) -> (-40, -6)
  line L3 (-35, 6) -> (-40, 6)
  line L4 (-35, -6) -> (-35, 6)
  line L5 (52.5, 6.3532) -> (52.5, -6.6468)
  line L6 (-47.5, 6.3532) -> (52.5, 6.3532)
  line L7 (-47.5, -6.6468) -> (-47.5, 6.3532)
  line L8 (52.5, -6.6468) -> (-47.5, -6.6468)
  line L9 (52.2, -6.347) -> (52.2, 6.353)
  line L10 (41.5, -6.347) -> (52.2, -6.347)
  line L11 (41.5, -4.4995) -> (41.5, -6.347)
  line L12 (41.5, -4.0099) -> (41.5, -4.4995)
  line L13 (39.5, -4.0099) -> (41.5, -4.0099)
  line L14 (39.5, 3.9901) -> (39.5, -4.0099)
  line L15 (41.5, 3.9901) -> (39.5, 3.9901)
  line L16 (41.5, 4.5005) -> (41.5, 3.9901)
  line L17 (41.5, 6.353) -> (41.5, 4.5005)
  line L18 (52.2, 6.353) -> (41.5, 6.353)
  line L19 (-45, 6) -> (-40, 6)
  line L20 (-45, -6) -> (-45, 6)
  line L21 (-40, -6) -> (-45, -6)
  line L22 (-40, -6) -> (-40, 6)
  point P4 (-40, 6)
  point P22 (-40, 6)
  point P3 (-40, -6)
  point P23 (-40, -6)
  horizontal L19
  vertical L20
  horizontal L21
  coincident P4 P22
  coincident P3 P23
extrude "拉伸31" cut sketch "草图27" profile of L2 L19 L20 L21 L22 against normal blind 34
extrude "拉伸32" cut of existing geometry blind -1
extrude "拉伸33" cut of existing geometry blind -1
extrude "拉伸34" add of existing geometry blind 40
extrude "拉伸35" add of existing geometry blind 5
sketch "草图28" plane through (-57.5, 0, 0) normal (-1, 0, 0) x axis (0, -1, 0)
  line L1 (9.5, 61) -> (9.5, -1.5)
  line L2 (-9.5, 61) -> (9.5, 61)
  line L3 (-9.5, 10) -> (-9.5, 61)
  line L4 (-9.5, -1.5) -> (-9.5, 10)
  line L5 (9.5, -1.5) -> (-9.5, -1.5)
  circle C1 centre (0, 57) radius 2
  point P7 (0, 57)
  dimension "d158" diameter C1 = 4
  dimension "d159" distance L2 P7 = 4
extrude "拉伸36" cut sketch "草图28" profile of C1 against normal blind 7

design "arm cover"
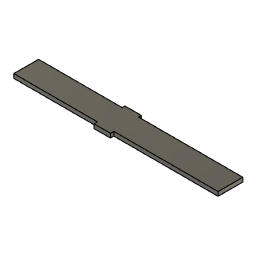
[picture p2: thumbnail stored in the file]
sketch "草图" plane through (0, 0, -20) normal (0, 0, -1) x axis (1, 0, 0)
  line L1 (-57.5, 9.5) -> (57.5, 9.5)
  line L2 (-57.5, -9.5) -> (-57.5, 9.5)
  line L3 (57.5, -9.5) -> (-57.5, -9.5)
  line L4 (57.5, 9.5) -> (57.5, -9.5)
  line L5 (-7.5, 8) -> (-7.5, 6.3532)
  line L6 (2.5, 8) -> (-7.5, 8)
  line L7 (2.5, 6.3532) -> (2.5, 8)
  line L8 (52.5, 6.3532) -> (2.5, 6.3532)
  line L9 (52.5, 5.5) -> (52.5, 6.3532)
  line L10 (52.5, -6.6468) -> (52.5, 5.5)
  line L11 (2.5, -6.6468) -> (52.5, -6.6468)
  line L12 (2.5, -8) -> (2.5, -6.6468)
  line L13 (-7.5, -8) -> (2.5, -8)
  line L14 (-7.5, -6.6468) -> (-7.5, -8)
  line L15 (-47.5, -6.6468) -> (-7.5, -6.6468)
  line L16 (-47.5, 6.3532) -> (-47.5, -6.6468)
  line L17 (-7.5, 6.3532) -> (-47.5, 6.3532)
  line L18 (-47.5, 6.3532) -> (-47.5, -6.6468)
  line L19 (52.5, -6.6468) -> (52.5, 6.3532)
  line L20 (-7.5, -8) -> (-7.5, -6.6468)
  line L21 (2.5, -8) -> (-7.5, -8)
  line L22 (2.5, -6.6468) -> (2.5, -8)
  line L23 (2.5, 8) -> (2.5, 6.3532)
  line L24 (-7.5, 8) -> (2.5, 8)
  line L25 (-7.5, 6.3532) -> (-7.5, 8)
  line L26 (2.5, -6.6468) -> (52.5, -6.6468)
  line L27 (-47.5, -6.6468) -> (-7.5, -6.6468)
  line L28 (-7.5, 6.3532) -> (-47.5, 6.3532)
  line L29 (52.5, 6.3532) -> (2.5, 6.3532)
  circle C1 centre (-51.5, 0) radius 1.5
  point P18 (-47.5, 6.3532)
  point P22 (-47.5, 6.3532)
  point P12 (52.5, -6.6468)
  point P20 (52.5, -6.6468)
  point P15 (-7.5, -8)
  point P26 (-7.5, -8)
  point P13 (2.5, -6.6468)
  point P24 (2.5, -6.6468)
  point P8 (2.5, 8)
  point P30 (2.5, 8)
  point P6 (-7.5, 6.3532)
  point P28 (-7.5, 6.3532)
  horizontal L26
  vertical L18
  horizontal L28
  vertical L19
  coincident P18 P22
  coincident P12 P20
  vertical L20
  horizontal L21
  vertical L22
  coincident P15 P26
  coincident P13 P24
  vertical L23
  horizontal L24
  vertical L25
  coincident P8 P30
  coincident P6 P28
  collinear L26 L27
  collinear L28 L29
extrude "拉伸2" new body sketch "草图" profile of L5 L6 L7 L8 L9 L10 L11 L12 L13 L14 L15 L16 L17 L27 L18 L29 L19 L20 L21 L22 L23 L24 L25 along normal blind 1
extrude "拉伸3" cut of existing geometry blind -1
extrude "拉伸4" cut of existing geometry blind -1
extrude "拉伸5" cut of existing geometry blind -1
extrude "拉伸6" cut of existing geometry blind -1
extrude "拉伸7" cut of existing geometry blind -0.5
extrude "拉伸8" cut of existing geometry blind -0.5
extrude "拉伸9" cut of existing geometry blind -0.5
extrude "拉伸10" cut of existing geometry blind -0.5
extrude "拉伸11" cut of existing geometry blind -0.5
extrude "拉伸12" cut of existing geometry blind -0.5
extrude "拉伸13" cut of existing geometry blind -0.5
extrude "拉伸14" cut of existing geometry blind -0.5
move "移动" TranslateX 0 TranslateY 0 TranslateZ 19.5
extrude "拉伸15" add of existing geometry blind 1

design "main 2"
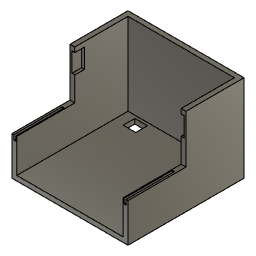
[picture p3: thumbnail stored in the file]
base_feature "基础特征"
sketch "草图" plane through (0, 0, 0) normal (0, 0, -1) x axis (1, 0, 0)
  line L1 (-32, -52) -> (-32, -40)
  line L2 (-45, -52) -> (-32, -52)
  line L3 (-45, -40) -> (-45, -52)
  line L4 (-32, -40) -> (-45, -40)
  line L5 (-60, 60) -> (60, 60)
  line L6 (-60, -60) -> (-60, 60)
  line L7 (60, -60) -> (-60, -60)
  line L8 (60, 60) -> (60, -60)
  line L9 (48, -50) -> (35, -50)
  line L10 (48, -37) -> (48, -50)
  line L11 (35, -37) -> (48, -37)
  line L12 (35, -50) -> (35, -37)
  point P10 (35, -50)
  point P11 (48, -50)
  horizontal L9
  vertical L10
  horizontal L11
  vertical L12
  dimension "d1" distance P10 P11 = 13
  dimension "d2" distance L9 L11 = 13
  dimension "d3" distance L7 L9 = 10
extrude "拉伸" cut sketch "草图" profile of L9 L10 L11 L12 against normal blind 30

design "arm2 v1"
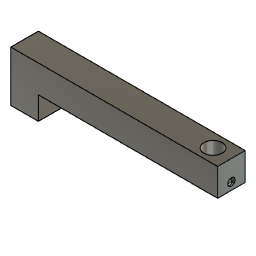
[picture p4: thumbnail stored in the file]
sketch "草图1" plane through (0, 0, 0) normal (0, 0, 1) x axis (1, 0, 0)
  line L1 (-7.5, 7.5) -> (7.5, 7.5)
  line L2 (-7.5, -7.5) -> (-7.5, 7.5)
  line L3 (7.5, -7.5) -> (-7.5, -7.5)
  line L4 (7.5, 7.5) -> (7.5, -7.5)
  line L5 (-7.5, -7.5) -> (7.5, 7.5)
  line L6 (7.5, -7.5) -> (-7.5, 7.5)
  point P6 (0, 0)
  point P1 (0, 0)
  point P4 (-7.5, -7.5)
  point P5 (7.5, -7.5)
  horizontal L1
  perpendicular L1 L2
  parallel L1 L3
  parallel L2 L4
  coincident L5 P6
  coincident L6 P6
  coincident P1 P6
  dimension "d1" distance P4 P5 = 15
  dimension "d2" distance L1 L3 = 15
sketch "草图2" plane through (0, 0, 0) normal (0, 1, 0) x axis (1, 0, 0)
  line L1 (0, -10) -> (0, 0)
  line L2 (87, -20) -> (10, -20)
  line L3 (0, -20) -> (10, -20)
  line L4 (0, -10) -> (0, -20)
  point P1 (0, 0)
  point P2 (0, 0)
  point P3 (0, -20)
  point P7 (0, -20)
  point P4 (87, -20)
  coincident P1 P2
  vertical L1
  perpendicular L1 L2
  coincident P3 L2
  coincident P3 L1
  coincident P3 P7
  dimension "d3" distance P2 P3 = 20
  dimension "d4" distance P3 P4 = 87
sweep "扫掠" sketch "草图1" TwistAngle 0 TaperAngle 0
sketch "草图5" plane through (0, 0, 0) normal (0, 0, -1) x axis (1, 0, 0)
  line L1 (7.5, 7.5) -> (7.5, -7.5)
  line L2 (-7.5, 7.5) -> (7.5, 7.5)
  line L3 (-7.5, -7.5) -> (-7.5, 7.5)
  line L4 (7.5, -7.5) -> (-7.5, -7.5)
  circle C1 centre (0, 0) radius 1.75
  point P1 (0, 0)
  point P10 (0, 0)
  coincident P1 P10
  dimension "d24" diameter C1 = 3.5
extrude "拉伸2" cut sketch "草图5" profile of C1 against normal blind 10
sketch "草图6" plane through (0, 0, 0) normal (0, 0, -1) x axis (1, 0, 0)
  line L1 (7.5, 7.5) -> (7.5, -7.5)
  line L2 (-7.5, 7.5) -> (7.5, 7.5)
  line L3 (-7.5, -7.5) -> (-7.5, 7.5)
  line L4 (7.5, -7.5) -> (-7.5, -7.5)
  line L5 (-6, 4) -> (-3, 4)
  line L6 (-6, -4) -> (-6, 4)
  line L7 (-3, -4) -> (-6, -4)
  line L8 (-3, 4) -> (-3, -4)
  line L9 (-6, -4) -> (-3, 4)
  line L10 (-3, -4) -> (-6, 4)
  circle C1 centre (0, 0) radius 1.75
  point P15 (-4.5, 0)
  point P13 (-6, -4)
  point P14 (-3, -4)
  point P1 (0, 0)
  horizontal L5
  perpendicular L5 L6
  parallel L5 L7
  parallel L6 L8
  coincident L9 P15
  coincident L10 P15
  dimension "d27" distance P13 P14 = 3
  dimension "d28" distance L5 L7 = 8
  dimension "d29" distance P1 P15 = 4.5
extrude "拉伸3" cut sketch "草图6" profile of L5 L6 L7 L8 against normal blind 10
sketch "草图7" plane through (-7.5, 0, 0) normal (-1, 0, 0) x axis (0, -1, 0)
  line L1 (7.5, 0) -> (-7.5, 0)
  line L2 (7.5, 27.5) -> (7.5, 0)
  line L3 (-7.5, 0) -> (-7.5, 27.5)
  line L4 (-7.5, 27.5) -> (7.5, 27.5)
  circle C1 centre (0, 4) radius 2
  point P6 (0, 4)
  dimension "d32" diameter C1 = 4
  dimension "d33" distance L1 P6 = 4
extrude "拉伸4" cut sketch "草图7" profile of C1 against normal blind 7.5
sketch "草图8" plane through (87, 0, 0) normal (1, 0, 0) x axis (0, 1, 0)
  line L1 (7.5, 12.5) -> (-7.5, 12.5)
  line L2 (7.5, 27.5) -> (7.5, 12.5)
  line L3 (-7.5, 27.5) -> (7.5, 27.5)
  line L4 (-7.5, 12.5) -> (-7.5, 27.5)
  line L5 (-7.5, 27.5) -> (7.5, 27.5)
  line L6 (-7.5, 72.5) -> (-7.5, 27.5)
  line L7 (7.5, 72.5) -> (-7.5, 72.5)
  line L8 (7.5, 27.5) -> (7.5, 72.5)
  line L9 (-7.5, 72.5) -> (7.5, 27.5)
  line L10 (7.5, 72.5) -> (-7.5, 27.5)
  point P10 (0, 50)
  point P4 (7.5, 27.5)
  point P6 (7.5, 27.5)
  horizontal L5
  perpendicular L5 L6
  parallel L5 L7
  parallel L6 L8
  coincident L9 P10
  coincident L10 P10
  coincident P4 P6
extrude "拉伸5" add sketch "草图8" profile of L1 L2 L3 L4 L5 L6 L7 L8 along normal blind 10
sketch "草图9" plane through (0, 0, 27.5) normal (0, 0, 1) x axis (-1, 0, 0)
  line L1 (-97, 7.5) -> (7.5, 7.5)
  line L2 (-97, -7.5) -> (-97, 7.5)
  line L3 (7.5, -7.5) -> (-97, -7.5)
  line L4 (7.5, 7.5) -> (7.5, -7.5)
  circle C1 centre (-94.5, -0.04) radius 4
  point P6 (-94.5, -0.04)
  dimension "d59" diameter C1 = 8
  dimension "d60" distance L2 P6 = 2.5
extrude "拉伸7" cut of existing geometry blind -2
extrude "拉伸9" add of existing geometry blind 10
sketch "草图11" plane through (0, 0, 27.5) normal (0, 0, 1) x axis (-1, 0, 0)
  line L1 (7.5, -7.5) -> (-105, -7.5)
  line L2 (7.5, 7.5) -> (7.5, -7.5)
  line L3 (-105, 7.5) -> (7.5, 7.5)
  line L4 (-105, -7.5) -> (-105, 7.5)
  circle C1 centre (-95, 0) radius 5
  dimension "d71" diameter C1 = 10
sketch "草图13" plane through (0, 0, 12.5) normal (0, 0, -1) x axis (1, 0, 0)
  line L1 (7.5, 7.5) -> (105, 7.5)
  line L2 (7.5, -7.5) -> (7.5, 7.5)
  line L3 (105, -7.5) -> (7.5, -7.5)
  line L4 (105, 7.5) -> (105, -7.5)
  line L5 (104, -4) -> (101, -4)
  line L6 (104, 4) -> (104, -4)
  line L7 (101, 4) -> (104, 4)
  line L8 (101, -4) -> (101, 4)
  line L9 (101, 0) -> (101, 0)
  point P10 (101, 0)
  point P6 (101, -4)
  point P7 (104, -4)
  horizontal L5
  vertical L6
  horizontal L7
  vertical L8
  coincident L8 P10
  perpendicular L6 L9
  dimension "d76" distance P6 P7 = 3
  dimension "d77" distance L5 L9 = 4
  dimension "d78" distance L5 L7 = 8
extrude "拉伸10" cut sketch "草图11" profile of C1 against normal blind 27
extrude "拉伸11" cut sketch "草图13" profile of L5 L6 L7 L8 against normal blind 10
sketch "草图14" plane through (105, 0, 0) normal (1, 0, 0) x axis (0, 1, 0)
  line L1 (7.5, 27.5) -> (7.5, 12.5)
  line L2 (-7.5, 27.5) -> (7.5, 27.5)
  line L3 (-7.5, 12.5) -> (-7.5, 27.5)
  line L4 (7.5, 12.5) -> (-7.5, 12.5)
sketch "草图15" plane through (105, 0, 0) normal (1, 0, 0) x axis (0, 1, 0)
  line L1 (7.5, 12.5) -> (-7.5, 12.5)
  circle C1 centre (0, 16.5) radius 2
  point P2 (0, 16.5)
  dimension "d81" diameter C1 = 4
  dimension "d82" distance P2 L1 = 4
extrude "拉伸12" cut sketch "草图15" profile of C1 against normal blind 8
